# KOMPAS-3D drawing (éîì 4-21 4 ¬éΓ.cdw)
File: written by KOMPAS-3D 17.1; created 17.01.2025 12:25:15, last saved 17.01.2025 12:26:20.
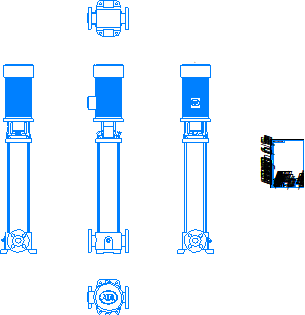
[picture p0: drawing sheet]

Sheet 1: A4, portrait

Title block, sheet 1: name: ВМН 4-21 4 кВт; designation: ВМН 4-21 4 кВт; material: Сталь 10  ГОСТ 1050-2013; mass: 53,9; sheets: 1; sheet format: A4; stored path: \\adlc.lan\data\АДЛ_ПКД\3D-модели\ADL production\Насосы ГРАНПАМП\Насосы ВМН\ВМН4\KOMPAS 3D\ВМН 4-21 4 кВт.cdw

Views: Вид 1, Спереди, Проекционный вид 2, Проекционный вид 3, Проекционный вид 4, Проекционный вид 5
Referenced files in \\adlc.lan\data\АДЛ_ПКД\3D-модели\ADL production\Насосы ГРАНПАМП\Насосы ВМН\ВМН4\KOMPAS 3D\: ВМН 4-21 4 кВт.m3d
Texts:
  Andrey
  АДЛ
Dimensions and other numbers on the sheet: 1:1; 1; 53,9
